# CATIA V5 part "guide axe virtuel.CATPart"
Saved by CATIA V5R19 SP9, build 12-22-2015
Part number: guide axe virtuel
Bounding box of the stored display mesh (mm): x -149.49 to 143.322, y -140 to 262.991, z 0 to 105
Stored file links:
  Z:\fausse table rondelle-20220905T211342Z-001\fausse table rondelle\guide axe virtuel.CATPart
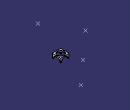
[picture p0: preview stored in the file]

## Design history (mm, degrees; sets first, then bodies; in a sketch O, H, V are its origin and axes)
AxisSystem1: origin (0, 0, 0), X (1, 0, 0), Y (0, 1, 0), Z (0, 0, 1)
Body1 (main body)
  Sketch1 on XY plane of AxisSystem1, origin (0, 0, 0), H (1, 0, 0), V (0, 1, 0)
    line L1 (25, 25) -> (25, -25)
    line L2 (25, -25) -> (-25, -25)
    line L3 (-25, -25) -> (-25, 25)
    line L4 (-25, 25) -> (25, 25)
    length L4 = 50
    length L1 = 50
    vertical: L1 V, L3 V
    horizontal: L2 H, L4 H
    equidistance: L1 L3 O, L2 L4 O
  Pad1: profile Sketch1, direction (0, 0, 1), length 25
  Sketch2 on YZ plane of AxisSystem1, origin (0, 0, 0), H (0, 1, 0), V (0, 0, 1)
    point P1 (0, 0)
  Hole1: placed by Sketch2, at (0, 0, 0) direction (-1, 0, 0), diameter 40, through (limit type 3)
  Sketch3 on face of Pad1 from Sketch1.L4, origin (0, 25, 2.6134), H (1, 0, 0), V (0, 0, -1)
    point P1 (0, 2.6134)
    reference projected point E1 (0, 2.6134) from edge [YZ plane of AxisSystem1 | XY plane of AxisSystem1]
    coincidence: P1 E1
  Hole2: placed by Sketch3, at (0, 25, 0) direction (0, -1, 0), diameter 40, through (limit type 3)
  Sketch4 on end face of Pad1, origin (10.8258, 14.1742, 25), H (1, 0, 0), V (0, 1, 0)
    point P1 (-10.8258, -14.1742)
    construction line L1 (-10.8258, 17.8328) -> (-10.8258, -46.1811)
    axis line L2 (-46.8104, -14.1742) -> (25.1588, -14.1742)
    reference intersected line E1 (14.1742, -39.1742) -> (-35.8258, -39.1742) from face of Pad1 from Sketch1.L2
    reference intersected line E2 (-35.8258, 10.8258) -> (14.1742, 10.8258) from face of Pad1 from Sketch1.L4
    reference intersected line E3 (14.1742, 10.8258) -> (14.1742, -39.1742) from face of Pad1 from Sketch1.L1
    reference intersected line E4 (-35.8258, -39.1742) -> (-35.8258, 10.8258) from face of Pad1 from Sketch1.L3
    vertical: L1 V
    horizontal: L2 H
    symmetry: E1 E2 L2, E3 E4 L1
    midpoint: P1 L1, P1 L2
  Hole3: placed by Sketch4, at (0, 0, 25) direction (0, 0, -1), diameter 40, through (limit type 3)
  DatumPoint1
  Point1: (0, 0, 0), relative to DatumPoint1, in AxisSystem1
  DatumPoint2
  DatumPoint3
  Point2: type Between, FirstPoint DatumPoint2, SecondPoint DatumPoint3, Ratio 0.5
  DatumSurface1
  Point3: type OnPlane, Support DatumSurface1, H 0, V 0, Direction (1, 0, 0), RefPoint Point2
